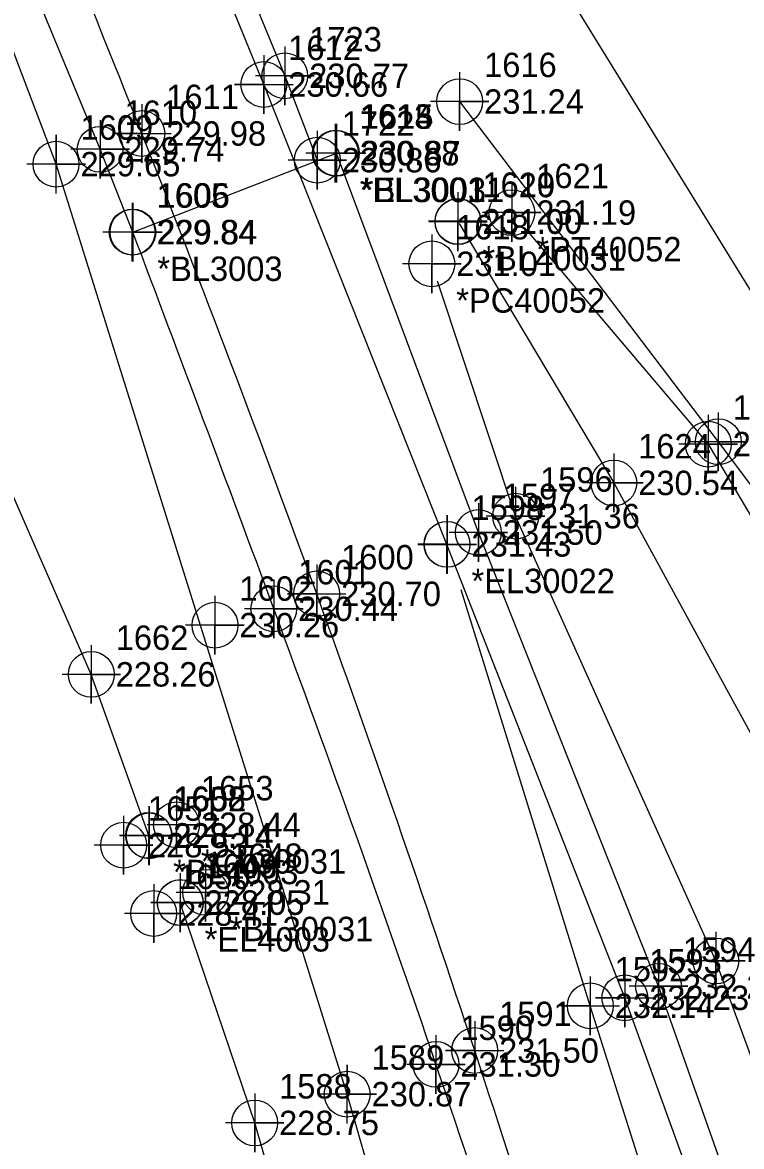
# Model space of a CAD drawing. Extents: x 2130962 to 2131465, y 643052 to 644206.
# Drawn here: x 2131080.2 to 2131153.9, y 643894.5 to 644009.5 of the extents above; entities that cross this region are included whole.
import ezdxf

# ---------------------------------------------------------------- set-up
doc = ezdxf.new("R2010")
doc.units = 0
for name, color, linetype in [('Exist DTM Breakline', 7, 'Continuous'), ('Exist DTM Breakline Cogo Comment', 7, 'Continuous'), ('Exist DTM Breakline Cogo Elevation', 7, 'Continuous'), ('Exist DTM Breakline Cogo Number', 7, 'Continuous'), ('Exist DTM Breakline Cogo Point CELL', 7, 'Continuous'), ('Exist DTM Drainline', 7, 'Continuous'), ('Exist DTM Drainline Cogo Comment', 7, 'Continuous'), ('Exist DTM Drainline Cogo Elevation', 7, 'Continuous'), ('Exist DTM Drainline Cogo Number', 7, 'Continuous'), ('Exist DTM Drainline Cogo Point CELL', 7, 'Continuous'), ('Exist Roads Change in Surface', 7, 'Continuous'), ('Exist Roads EOP', 7, 'Continuous'), ('Exist Roads EOP Cogo Comment', 7, 'Continuous'), ('Exist Roads EOP Cogo Elevation', 7, 'Continuous'), ('Exist Roads EOP Cogo Number', 7, 'Continuous'), ('Exist Roads EOP Cogo Point CELL', 7, 'Continuous'), ('Exist Roads EOP Other Cogo Comment', 7, 'Continuous'), ('Exist Roads EOP Other Cogo Elevation', 7, 'Continuous'), ('Exist Roads EOP Other Cogo Number', 7, 'Continuous'), ('Exist Roads EOP Other Cogo Point CELL', 7, 'Continuous'), ('Exist Roads EOT', 7, 'Continuous'), ('Exist Roads EOT Cogo Comment', 7, 'Continuous'), ('Exist Roads EOT Cogo Elevation', 7, 'Continuous'), ('Exist Roads EOT Cogo Number', 7, 'Continuous'), ('Exist Roads EOT Cogo Point CELL', 7, 'Continuous'), ('Exist Roads Soil', 7, 'Continuous'), ('Exist Roads Soil Cogo Elevation', 7, 'Continuous'), ('Exist Roads Soil Cogo Number', 7, 'Continuous'), ('Exist Roads Soil Cogo Point CELL', 7, 'Continuous')]:
    doc.layers.add(name, color=color, linetype=linetype)

msp = doc.modelspace()

# ---------------------------------------------------------------- linework, layer by layer
at = {"layer": 'Exist DTM Breakline'}
msp.add_line((2131131.9257, 643988.1771), (2131150.4586, 643966.3443), dxfattribs=at)
for points in [[(2131081.0395, 644071.409), (2131092.8041, 644038.758), (2131107.0869, 644004.0369), (2131110.421, 643995.4078)], [(2131266.3306, 643269.372), (2131264.0776, 643319.4437), (2131258.8396, 643369.5498), (2131255.3671, 643419.5794), (2131249.6414, 643469.556), (2131244.7652, 643520.0623), (2131238.8778, 643569.4077), (2131228.6495, 643620.6699), (2131219.85, 643669.4823), (2131206.9682, 643717.8453), (2131195.8132, 643768.1497), (2131183.2404, 643816.8151), (2131169.0496, 643865.1461), (2131151.2314, 643913.4424), (2131130.7295, 643958.9736), (2131122.7411, 643983.0115)], [(2131150.4586, 643966.3443), (2131176.896, 643921.8304), (2131203.4733, 643877.1362), (2131230.3046, 643833.1199)]]:
    msp.add_lwpolyline(points, dxfattribs=at)
at = {"layer": 'Exist DTM Breakline Cogo Point CELL'}
for points in [[(2131107.0869, 644007.0369), (2131107.0869, 644001.0369), (2131107.0869, 644004.0369), (2131110.0869, 644004.0369), (2131104.0869, 644004.0369)], [(2131110.421, 643998.4078), (2131110.421, 643992.4078), (2131110.421, 643995.4078), (2131113.421, 643995.4078), (2131107.421, 643995.4078)], [(2131130.3456, 643993.0386), (2131130.3456, 643987.0386), (2131130.3456, 643990.0386), (2131133.3456, 643990.0386), (2131127.3456, 643990.0386)], [(2131124.823, 643992.1466), (2131124.823, 643986.1466), (2131124.823, 643989.1466), (2131127.823, 643989.1466), (2131121.823, 643989.1466)], [(2131122.148, 643987.7962), (2131122.148, 643981.7962), (2131122.148, 643984.7962), (2131125.148, 643984.7962), (2131119.148, 643984.7962)], [(2131150.4586, 643969.3443), (2131150.4586, 643963.3443), (2131150.4586, 643966.3443), (2131153.4586, 643966.3443), (2131147.4586, 643966.3443)], [(2131130.7295, 643961.9736), (2131130.7295, 643955.9736), (2131130.7295, 643958.9736), (2131133.7295, 643958.9736), (2131127.7295, 643958.9736)], [(2131099.9361, 643950.8098), (2131099.9361, 643944.8098), (2131099.9361, 643947.8098), (2131102.9361, 643947.8098), (2131096.9361, 643947.8098)], [(2131151.2314, 643916.4424), (2131151.2314, 643910.4424), (2131151.2314, 643913.4424), (2131154.2314, 643913.4424), (2131148.2314, 643913.4424)]]:
    msp.add_lwpolyline(points, dxfattribs=at)
for centre in [(2131107.0869, 644004.0369), (2131110.421, 643995.4078), (2131130.3456, 643990.0386), (2131124.823, 643989.1466), (2131122.148, 643984.7962), (2131150.4586, 643966.3443), (2131130.7295, 643958.9736), (2131099.9361, 643947.8098), (2131151.2314, 643913.4424)]:
    msp.add_circle(centre, 2.344, dxfattribs=at)
at = {"layer": 'Exist DTM Drainline'}
for points in [[(2131093.1541, 643926.3006), (2131087.2748, 643942.7791), (2131067.2265, 643988.5191), (2131050.4927, 644034.5509), (2131030.3027, 644079.1881), (2131009.8205, 644123.8359), (2130986.2155, 644168.1871)], [(2131124.9344, 643988.9242), (2131140.7825, 643962.3724), (2131165.6632, 643916.8402), (2131169.9073, 643908.436)], [(2131000.2029, 643226.7228), (2131050.9884, 643228.9032), (2131099.0297, 643228.5605), (2131120.2968, 643239.3591), (2131144.9156, 643253.3469), (2131146.4739, 643252.3674), (2131154.3188, 643256.8046), (2131168.9618, 643265.5132), (2131176.6257, 643272.964), (2131179.8144, 643285.303), (2131183.3842, 643315.022), (2131190.1471, 643365.8731), (2131190.1489, 643413.686), (2131192.3886, 643466.4632), (2131188.8083, 643512.615), (2131184.0059, 643563.7066), (2131175.3, 643610.7482), (2131168.3784, 643658.7431), (2131156.7476, 643707.4708), (2131144.9036, 643754.0458), (2131132.9438, 643802.544), (2131118.0831, 643847.9475), (2131104.0084, 643896.8663), (2131096.3866, 643919.4077)]]:
    msp.add_lwpolyline(points, dxfattribs=at)
at = {"layer": 'Exist DTM Drainline Cogo Point CELL'}
for points in [[(2131124.8265, 643992.105), (2131124.8265, 643986.105), (2131124.8265, 643989.105), (2131127.8265, 643989.105), (2131121.8265, 643989.105)], [(2131140.7825, 643965.3724), (2131140.7825, 643959.3724), (2131140.7825, 643962.3724), (2131143.7825, 643962.3724), (2131137.7825, 643962.3724)], [(2131087.2748, 643945.7791), (2131087.2748, 643939.7791), (2131087.2748, 643942.7791), (2131090.2748, 643942.7791), (2131084.2748, 643942.7791)], [(2131093.1541, 643929.3006), (2131093.1541, 643923.3006), (2131093.1541, 643926.3006), (2131096.1541, 643926.3006), (2131090.1541, 643926.3006)], [(2131096.3866, 643922.4077), (2131096.3866, 643916.4077), (2131096.3866, 643919.4077), (2131099.3866, 643919.4077), (2131093.3866, 643919.4077)], [(2131104.0084, 643899.8663), (2131104.0084, 643893.8663), (2131104.0084, 643896.8663), (2131107.0084, 643896.8663), (2131101.0084, 643896.8663)]]:
    msp.add_lwpolyline(points, dxfattribs=at)
for centre in [(2131124.8265, 643989.105), (2131140.7825, 643962.3724), (2131087.2748, 643942.7791), (2131093.1541, 643926.3006), (2131096.3866, 643919.4077), (2131104.0084, 643896.8663)]:
    msp.add_circle(centre, 2.344, dxfattribs=at)
at = {"layer": 'Exist Roads Change in Surface'}
msp.add_line((2131091.5349, 643988.0437), (2131112.374, 643996.1136), dxfattribs=at)
at = {"layer": 'Exist Roads EOP'}
for points in [[(2131091.5349, 643988.0437), (2131088.176, 643996.5155), (2131069.4781, 644041.6508), (2131049.1592, 644087.3902), (2131027.8514, 644132.1094), (2131005.2923, 644177.6183)], [(2131124.9979, 644001.4036), (2131151.4846, 643966.5856), (2131158.5905, 643957.1022), (2131179.4402, 643923.1833), (2131206.9257, 643878.7542), (2131233.5521, 643835.7453)], [(2131264.2715, 643222.5647), (2131259.8757, 643269.3254), (2131257.0196, 643319.4043), (2131254.2561, 643369.6499), (2131250.0777, 643419.4187), (2131246.1511, 643469.0294), (2131240.8382, 643519.1271), (2131234.3674, 643568.5584), (2131226.3321, 643620.1808), (2131217.0271, 643668.7116), (2131205.6213, 643717.607), (2131192.0578, 643767.2595), (2131177.9714, 643815.0911), (2131162.2913, 643862.9344), (2131145.3604, 643910.8486), (2131126.9113, 643957.2915), (2131112.3691, 643996.1228)]]:
    msp.add_lwpolyline(points, dxfattribs=at)
msp.add_spline([(2131166.2495, 643216.6951), (2131171.8131, 643218.7244), (2131182.3713, 643223.9726), (2131191.8117, 643231.1489), (2131200.5013, 643239.6993), (2131208.8071, 643249.0697), (2131216.0672, 643259.0032), (2131218.7188, 643264.347), (2131220.5363, 643270.0958), (2131222.8445, 643282.0077), (2131224.3583, 643293.9245), (2131224.8763, 643317.7904), (2131222.0632, 643367.6716), (2131218.5448, 643416.8114), (2131214.3187, 643466.3462), (2131209.1735, 643515.6666), (2131202.7939, 643565.1545), (2131195.0475, 643613.9937), (2131186.4014, 643662.4763), (2131176.0113, 643711.405), (2131164.6154, 643759.8896), (2131151.874, 643807.8526), (2131137.8554, 643855.4065), (2131122.5733, 643902.8574), (2131105.9622, 643949.4862), (2131091.5349, 643988.0437)], degree=3, dxfattribs=at)
at = {"layer": 'Exist Roads EOP Cogo Point CELL'}
for points in [[(2131112.258, 643999.1179), (2131112.258, 643993.1179), (2131112.258, 643996.1179), (2131115.258, 643996.1179), (2131109.258, 643996.1179)], [(2131112.3691, 643999.1228), (2131112.3691, 643993.1228), (2131112.3691, 643996.1228), (2131115.3691, 643996.1228), (2131109.3691, 643996.1228)], [(2131091.4589, 643991.0422), (2131091.4589, 643985.0422), (2131091.4589, 643988.0422), (2131094.4589, 643988.0422), (2131088.4589, 643988.0422)], [(2131126.9113, 643960.2915), (2131126.9113, 643954.2915), (2131126.9113, 643957.2915), (2131129.9113, 643957.2915), (2131123.9113, 643957.2915)], [(2131105.9622, 643952.4862), (2131105.9622, 643946.4862), (2131105.9622, 643949.4862), (2131108.9622, 643949.4862), (2131102.9622, 643949.4862)], [(2131145.3604, 643913.8486), (2131145.3604, 643907.8486), (2131145.3604, 643910.8486), (2131148.3604, 643910.8486), (2131142.3604, 643910.8486)], [(2131122.5733, 643905.8574), (2131122.5733, 643899.8574), (2131122.5733, 643902.8574), (2131125.5733, 643902.8574), (2131119.5733, 643902.8574)]]:
    msp.add_lwpolyline(points, dxfattribs=at)
for centre in [(2131112.258, 643996.1179), (2131112.3691, 643996.1228), (2131091.4589, 643988.0422), (2131126.9113, 643957.2915), (2131105.9622, 643949.4862), (2131145.3604, 643910.8486), (2131122.5733, 643902.8574)]:
    msp.add_circle(centre, 2.344, dxfattribs=at)
at = {"layer": 'Exist Roads EOP Other Cogo Point CELL'}
for points in [[(2131124.9979, 644004.4036), (2131124.9979, 643998.4036), (2131124.9979, 644001.4036), (2131127.9979, 644001.4036), (2131121.9979, 644001.4036)], [(2131088.176, 643999.5155), (2131088.176, 643993.5155), (2131088.176, 643996.5155), (2131091.176, 643996.5155), (2131085.176, 643996.5155)], [(2131112.374, 643999.1136), (2131112.374, 643993.1136), (2131112.374, 643996.1136), (2131115.374, 643996.1136), (2131109.374, 643996.1136)], [(2131091.5349, 643991.0437), (2131091.5349, 643985.0437), (2131091.5349, 643988.0437), (2131094.5349, 643988.0437), (2131088.5349, 643988.0437)], [(2131151.4846, 643969.5856), (2131151.4846, 643963.5856), (2131151.4846, 643966.5856), (2131154.4846, 643966.5856), (2131148.4846, 643966.5856)], [(2131096.0018, 643930.3806), (2131096.0018, 643924.3806), (2131096.0018, 643927.3806), (2131099.0018, 643927.3806), (2131093.0018, 643927.3806)], [(2131093.2049, 643929.2499), (2131093.2049, 643923.2499), (2131093.2049, 643926.2499), (2131096.2049, 643926.2499), (2131090.2049, 643926.2499)], [(2131090.5826, 643928.2924), (2131090.5826, 643922.2924), (2131090.5826, 643925.2924), (2131093.5826, 643925.2924), (2131087.5826, 643925.2924)], [(2131098.9792, 643923.4673), (2131098.9792, 643917.4673), (2131098.9792, 643920.4673), (2131101.9792, 643920.4673), (2131095.9792, 643920.4673)], [(2131096.3736, 643922.4214), (2131096.3736, 643916.4214), (2131096.3736, 643919.4214), (2131099.3736, 643919.4214), (2131093.3736, 643919.4214)], [(2131093.6652, 643921.2979), (2131093.6652, 643915.2979), (2131093.6652, 643918.2979), (2131096.6652, 643918.2979), (2131090.6652, 643918.2979)]]:
    msp.add_lwpolyline(points, dxfattribs=at)
for centre in [(2131124.9979, 644001.4036), (2131088.176, 643996.5155), (2131112.374, 643996.1136), (2131091.5349, 643988.0437), (2131151.4846, 643966.5856), (2131096.0018, 643927.3806), (2131093.2049, 643926.2499), (2131090.5826, 643925.2924), (2131098.9792, 643920.4673), (2131096.3736, 643919.4214), (2131093.6652, 643918.2979)]:
    msp.add_circle(centre, 2.344, dxfattribs=at)
at = {"layer": 'Exist Roads EOT'}
for points in [[(2131027.1782, 644188.3908), (2131054.4288, 644144.4752), (2131080.5567, 644102.0812), (2131108.007, 644057.7457), (2131134.6373, 644014.7205), (2131162.4421, 643969.638), (2131189.8746, 643925.4695), (2131217.6277, 643880.5724), (2131241.9317, 643841.1922)], [(2131255.7894, 643269.2666), (2131252.7511, 643319.2443), (2131249.9083, 643369.5477), (2131246.3502, 643419.1778), (2131242.1933, 643468.6938), (2131237.0867, 643518.9193), (2131230.8671, 643568.2588), (2131222.7066, 643619.1047), (2131213.6442, 643668.3078), (2131202.755, 643717.0933), (2131189.234, 643766.4577), (2131174.9499, 643814.1787), (2131159.2111, 643861.933), (2131141.9103, 643909.6722), (2131123.7008, 643956.0828), (2131104.9436, 644003.1503), (2131086.2706, 644048.8072), (2131065.6997, 644094.9191), (2131044.3618, 644140.0645), (2131021.6804, 644185.4526)], [(2131237.6994, 643363.706), (2131234.1644, 643418.0043), (2131229.8934, 643468.0098), (2131225.1139, 643518.3873), (2131218.7748, 643566.6133), (2131210.7043, 643617.3811), (2131201.4139, 643666.7928), (2131191.4121, 643714.0755), (2131179.6696, 643764.3904), (2131167.3006, 643812.1237), (2131153.7359, 643860.4033), (2131138.3711, 643908.8544), (2131125.1607, 643951.4161)]]:
    msp.add_lwpolyline(points, dxfattribs=at)
msp.add_spline([(2131166.718, 643215.2083), (2131172.3866, 643217.1804), (2131211.4056, 643247.1499), (2131223.758, 643268.7314), (2131228.3848, 643317.935), (2131225.533, 643367.8628), (2131222.2486, 643417.1873), (2131217.9619, 643466.6275), (2131212.8794, 643516.2377), (2131206.5633, 643565.5764), (2131198.9021, 643614.6757), (2131189.6851, 643663.4055), (2131179.3985, 643712.1311), (2131168.3085, 643760.7185), (2131155.755, 643808.9129), (2131141.6748, 643856.5528), (2131126.5354, 643904.2758), (2131110.3559, 643951.0191), (2131092.4533, 643998.1348), (2131073.722, 644043.631), (2131053.1654, 644089.359), (2131032.0052, 644134.0908), (2131009.0644, 644179.3802)], degree=3, dxfattribs=at)
at = {"layer": 'Exist Roads EOT Cogo Point CELL'}
for points in [[(2131104.9436, 644006.1503), (2131104.9436, 644000.1503), (2131104.9436, 644003.1503), (2131101.9436, 644003.1503), (2131107.9436, 644003.1503)], [(2131092.4533, 644001.1348), (2131092.4533, 643995.1348), (2131092.4533, 643998.1348), (2131089.4533, 643998.1348), (2131095.4533, 643998.1348)], [(2131123.7008, 643959.0828), (2131123.7008, 643953.0828), (2131123.7008, 643956.0828), (2131120.7008, 643956.0828), (2131126.7008, 643956.0828)], [(2131123.7111, 643959.0865), (2131123.7111, 643953.0865), (2131123.7111, 643956.0865), (2131120.7111, 643956.0865), (2131126.7111, 643956.0865)], [(2131110.3559, 643954.0191), (2131110.3559, 643948.0191), (2131110.3559, 643951.0191), (2131107.3559, 643951.0191), (2131113.3559, 643951.0191)], [(2131141.9103, 643912.6722), (2131141.9103, 643906.6722), (2131141.9103, 643909.6722), (2131138.9103, 643909.6722), (2131144.9103, 643909.6722)], [(2131138.3711, 643911.8544), (2131138.3711, 643905.8544), (2131138.3711, 643908.8544), (2131135.3711, 643908.8544), (2131141.3711, 643908.8544)], [(2131126.5354, 643907.2758), (2131126.5354, 643901.2758), (2131126.5354, 643904.2758), (2131123.5354, 643904.2758), (2131129.5354, 643904.2758)]]:
    msp.add_lwpolyline(points, dxfattribs=at)
for centre in [(2131104.9436, 644003.1503), (2131092.4533, 643998.1348), (2131123.7008, 643956.0828), (2131123.7111, 643956.0865), (2131110.3559, 643951.0191), (2131138.3711, 643908.8544), (2131141.9103, 643909.6722), (2131126.5354, 643904.2758)]:
    msp.add_circle(centre, 2.344, dxfattribs=at)
at = {"layer": 'Exist Roads Soil'}
msp.add_lwpolyline([(2131224.8674, 643317.753), (2131220.141, 643317.6487), (2131216.7544, 643367.544), (2131211.084, 643416.163), (2131207.4344, 643466.363), (2131202.1097, 643514.7948), (2131195.0195, 643564.3052), (2131187.2605, 643612.6498), (2131179.506, 643660.9545), (2131164.8317, 643709.0781), (2131153.9175, 643755.9834), (2131140.8896, 643804.492), (2131127.2512, 643851.9231), (2131113.4771, 643899.8082), (2131083.6685, 643994.997), (2131066.191, 644040.9476), (2131049.1539, 644087.3869)], dxfattribs=at)
at = {"layer": 'Exist Roads Soil Cogo Point CELL'}
for points in [[(2131083.6685, 643991.997), (2131083.6685, 643997.997), (2131083.6685, 643994.997), (2131086.6685, 643994.997), (2131080.6685, 643994.997)], [(2131113.4771, 643896.8082), (2131113.4771, 643902.8082), (2131113.4771, 643899.8082), (2131116.4771, 643899.8082), (2131110.4771, 643899.8082)]]:
    msp.add_lwpolyline(points, dxfattribs=at)
for centre in [(2131083.6685, 643994.997), (2131113.4771, 643899.8082)]:
    msp.add_circle(centre, 2.344, dxfattribs=at)

# ---------------------------------------------------------------- texts
at = {"layer": 'Exist DTM Breakline Cogo Comment'}
for s, p in [('*PT40052', (2131132.8456, 643985.0386)), ('*PC40052', (2131124.648, 643979.7962))]:
    msp.add_text(s, height=2.5, dxfattribs=at).set_placement(p)
at = {"layer": 'Exist DTM Breakline Cogo Elevation'}
for s, p in [('230.77', (2131109.5869, 644002.7869)), ('230.86', (2131112.921, 643994.1578)), ('231.19', (2131132.8456, 643988.7886)), ('231.00', (2131127.323, 643987.8966)), ('231.01', (2131124.648, 643983.5462)), ('231.38', (2131152.9586, 643965.0943)), ('231.36', (2131133.2295, 643957.7236)), ('230.26', (2131102.4361, 643946.5598))]:
    msp.add_text(s, height=2.5, dxfattribs=at).set_placement(p)
at = {"layer": 'Exist DTM Breakline Cogo Number'}
for s, p in [('1723', (2131109.5869, 644006.5369)), ('1722', (2131112.921, 643997.9078)), ('1619', (2131127.323, 643991.6466)), ('1621', (2131132.8456, 643992.5386)), ('1618', (2131124.648, 643987.2962)), ('1623', (2131152.9586, 643968.8443)), ('1596', (2131133.2295, 643961.4736)), ('1602', (2131102.4361, 643950.3098))]:
    msp.add_text(s, height=2.5, dxfattribs=at).set_placement(p)
at = {"layer": 'Exist DTM Drainline Cogo Comment'}
for s, p in [('*BL40031', (2131127.3265, 643984.105)), ('*BL4003', (2131095.6541, 643921.3006)), ('*EL4003', (2131098.8866, 643914.4077))]:
    msp.add_text(s, height=2.5, dxfattribs=at).set_placement(p)
at = {"layer": 'Exist DTM Drainline Cogo Elevation'}
for s, p in [('231.00', (2131127.3265, 643987.855)), ('230.54', (2131143.2825, 643961.1224)), ('228.26', (2131089.7748, 643941.5291)), ('228.14', (2131095.6541, 643925.0506)), ('228.05', (2131098.8866, 643918.1577)), ('228.75', (2131106.5084, 643895.6163))]:
    msp.add_text(s, height=2.5, dxfattribs=at).set_placement(p)
at = {"layer": 'Exist DTM Drainline Cogo Number'}
for s, p in [('1620', (2131127.3265, 643991.605)), ('1624', (2131143.2825, 643964.8724)), ('1662', (2131089.7748, 643945.2791)), ('1608', (2131095.6541, 643928.8006)), ('1603', (2131098.8866, 643921.9077)), ('1588', (2131106.5084, 643899.3663))]:
    msp.add_text(s, height=2.5, dxfattribs=at).set_placement(p)
at = {"layer": 'Exist Roads EOP Cogo Comment'}
for s, p in [('*EL3001', (2131114.758, 643991.1179)), ('*EL30011', (2131114.8691, 643991.1228))]:
    msp.add_text(s, height=2.5, dxfattribs=at).set_placement(p)
at = {"layer": 'Exist Roads EOP Cogo Elevation'}
for s, p in [('230.88', (2131114.758, 643994.8679)), ('230.87', (2131114.8691, 643994.8728)), ('229.84', (2131093.9589, 643986.7922)), ('231.50', (2131129.4113, 643956.0415)), ('230.44', (2131108.4622, 643948.2362)), ('232.22', (2131147.8604, 643909.5986)), ('231.30', (2131125.0733, 643901.6074))]:
    msp.add_text(s, height=2.5, dxfattribs=at).set_placement(p)
at = {"layer": 'Exist Roads EOP Cogo Number'}
for s, p in [('1613', (2131114.758, 643998.6179)), ('1614', (2131114.8691, 643998.6228)), ('1605', (2131093.9589, 643990.5422)), ('1597', (2131129.4113, 643959.7915)), ('1601', (2131108.4622, 643951.9862)), ('1594', (2131147.8604, 643913.3486)), ('1590', (2131125.0733, 643905.3574))]:
    msp.add_text(s, height=2.5, dxfattribs=at).set_placement(p)
at = {"layer": 'Exist Roads EOP Other Cogo Comment'}
for s, p in [('*BL30031', (2131114.874, 643991.1136)), ('*BL3003', (2131094.0349, 643983.0437)), ('*CL30031', (2131098.5018, 643922.3806)), ('*BL30031', (2131101.4792, 643915.4673))]:
    msp.add_text(s, height=2.5, dxfattribs=at).set_placement(p)
at = {"layer": 'Exist Roads EOP Other Cogo Elevation'}
for s, p in [('231.24', (2131127.4979, 644000.1536)), ('229.74', (2131090.676, 643995.2655)), ('230.87', (2131114.874, 643994.8636)), ('229.84', (2131094.0349, 643986.7937)), ('228.44', (2131098.5018, 643926.1306)), ('228.14', (2131095.7049, 643924.9999)), ('228.53', (2131093.0826, 643924.0424)), ('228.31', (2131101.4792, 643919.2173)), ('228.05', (2131098.8736, 643918.1714)), ('228.41', (2131096.1652, 643917.0479))]:
    msp.add_text(s, height=2.5, dxfattribs=at).set_placement(p)
at = {"layer": 'Exist Roads EOP Other Cogo Number'}
for s, p in [('1616', (2131127.4979, 644003.9036)), ('1610', (2131090.676, 643999.0155)), ('1615', (2131114.874, 643998.6136)), ('1606', (2131094.0349, 643990.5437)), ('1653', (2131098.5018, 643929.8806)), ('1652', (2131095.7049, 643928.7499)), ('1651', (2131093.0826, 643927.7924)), ('1648', (2131101.4792, 643922.9673)), ('1649', (2131098.8736, 643921.9214)), ('1650', (2131096.1652, 643920.7979))]:
    msp.add_text(s, height=2.5, dxfattribs=at).set_placement(p)
at = {"layer": 'Exist Roads EOT Cogo Comment'}
msp.add_text('*EL30022', height=2.5, dxfattribs=at).set_placement((2131126.2111, 643951.0865))
at = {"layer": 'Exist Roads EOT Cogo Elevation'}
for s, p in [('230.66', (2131107.4436, 644001.9003)), ('229.98', (2131094.9533, 643996.8848)), ('231.43', (2131126.2008, 643954.8328)), ('231.43', (2131126.2111, 643954.8365)), ('230.70', (2131112.8559, 643949.7691)), ('232.14', (2131140.8711, 643907.6044)), ('232.23', (2131144.4103, 643908.4222)), ('231.50', (2131129.0354, 643903.0258))]:
    msp.add_text(s, height=2.5, dxfattribs=at).set_placement(p)
at = {"layer": 'Exist Roads EOT Cogo Number'}
for s, p in [('1612', (2131107.4436, 644005.6503)), ('1611', (2131094.9533, 644000.6348)), ('1598', (2131126.2008, 643958.5828)), ('1599', (2131126.2111, 643958.5865)), ('1600', (2131112.8559, 643953.5191)), ('1593', (2131144.4103, 643912.1722)), ('1592', (2131140.8711, 643911.3544)), ('1591', (2131129.0354, 643906.7758))]:
    msp.add_text(s, height=2.5, dxfattribs=at).set_placement(p)
at = {"layer": 'Exist Roads Soil Cogo Elevation'}
for s, p in [('229.65', (2131086.1685, 643993.747)), ('230.87', (2131115.9771, 643898.5582))]:
    msp.add_text(s, height=2.5, dxfattribs=at).set_placement(p)
at = {"layer": 'Exist Roads Soil Cogo Number'}
for s, p in [('1609', (2131086.1685, 643997.497)), ('1589', (2131115.9771, 643902.3082))]:
    msp.add_text(s, height=2.5, dxfattribs=at).set_placement(p)

doc.saveas('drawing.dxf')
